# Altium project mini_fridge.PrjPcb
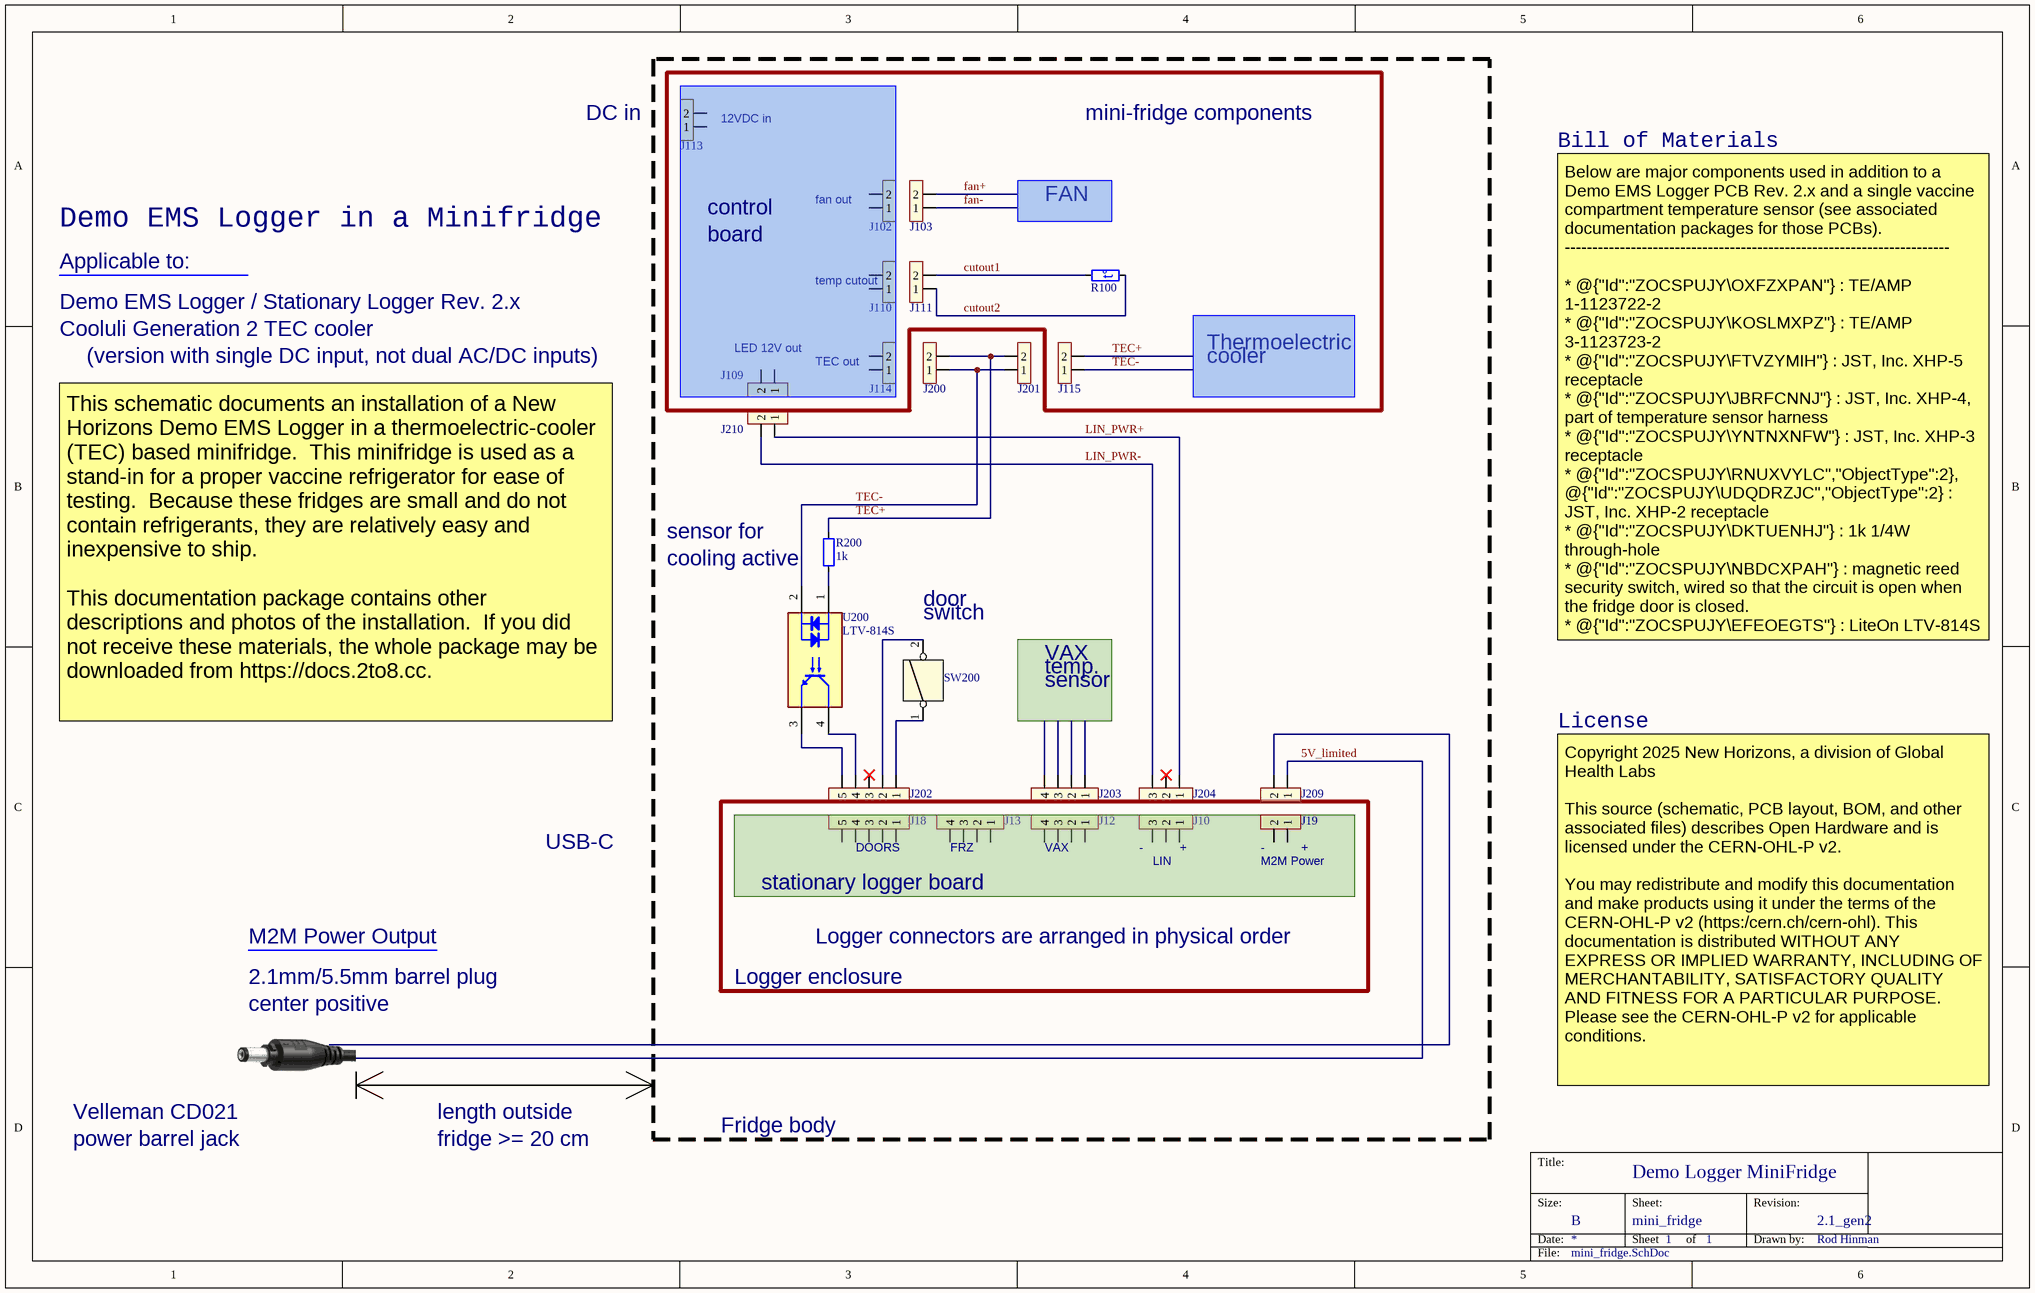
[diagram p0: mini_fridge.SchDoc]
nhToday: 2025-06-04; nhProjRev: 2.1_gen2; nhProjName: Demo Logger MiniFridge; nhEngPhone: +1 808-989-0977; nhEngName: Rod Hinman; nhEngEmail: rhinman@nhgh.org
1 sheet, 24 parts. Net scope: global (net labels, ports and power ports of the same name join across sheets).
Board file: mini_fridge.PcbDoc

## Sheet mini_fridge.SchDoc: Insert Title
size B; DrawnBy: Insert Name; Organization: NH-GG; DocumentNumber: 12345; Revision: 1; SheetNumber: 1; SheetTotal: 1; nhSheetName: mini_fridge

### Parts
J10  JST XH  [JST_S3B-XH-A(LF)(SN)]  (value not drawn)
J12  JST XH  [JST_B4B-XH-AM(LF)(SN)]  (value not drawn)
J13  JST XH  [JST_B4B-XH-AM(LF)(SN)]  (value not drawn)
J18  JST XH  [JST_S5B-XH-A(LF)(SN)]  (value not drawn)
J19  1x2 3.96mm  [AMP_1-1123723-2]  (value not drawn)
J102  1x2 3.96mm  [AMP_1-1123723-2]  (value not drawn)
J103  1x2 3.96mm  [AMP_1-1123723-2]  (value not drawn)
J109  1x2 3.96mm  [AMP_1-1123723-2]  (value not drawn)
J110  1x2 3.96mm  [AMP_1-1123723-2]  (value not drawn)
J111  1x2 3.96mm  [AMP_1-1123723-2]  (value not drawn)
J113  1x2 3.96mm  [AMP_1-1123723-2]  (value not drawn)
J114  1x2 3.96mm  [AMP_1-1123723-2]  (value not drawn)
J115  1x2 3.96mm  [AMP_1-1123723-2]  (value not drawn)
J200  1x2 3.96mm  [AMP_1-1123723-2]  (value not drawn)
J201  1x2 3.96mm  [AMP_1-1123723-2]  (value not drawn)
J202  JST XH  [JST_S5B-XH-A(LF)(SN)]  (value not drawn)
J203  JST XH  [JST_B4B-XH-AM(LF)(SN)]  (value not drawn)
J204  JST XH  [JST_S3B-XH-A(LF)(SN)]  (value not drawn)
J209  1x2 3.96mm  [AMP_1-1123723-2]  (value not drawn)
J210  1x2 3.96mm  [AMP_1-1123723-2]  (value not drawn)
R100  B2585:3435K 0402 1%  [RESC1005X40[0402]]  (value not drawn)
R200  value_text: 1k  [RESC1608X05AN[0603]]  (hidden comment: 1/10W 0603 1%)
SW200  SPST-NO Off-Mom  [CH_MX1A-11NW]  (value not drawn)
U200  LTV-814S  [DIP4_SMD]

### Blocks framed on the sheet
stationary logger board: J10 J12 J13 J18 J19

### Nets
5V_limited: J209.1
cutout1: J111.2 R100.1
cutout2: J111.1 R100.2
fan+: J103.2
fan-: J103.1
LIN_PWR+: J204.1 J210.1
LIN_PWR-: J204.3 J210.2
TEC+: J115.2 J200.2 J201.2 R200.1
TEC-: J115.1 J200.1 J201.1 U200.2(Cathode)
NetJ202_1: J202.1 SW200.1
NetJ202_2: J202.2 SW200.2
NetJ202_4: J202.4 U200.4(Collector)
NetJ202_5: J202.5 U200.3(Emitter)
NetR200_2: R200.2 U200.1(Anode)

Not connected (* = marked no-connect by the designer): J10 1 2 3; J12 1 2 3 4; J13 1 2 3 4; J18 1 2 3 4 5; J19 1 2; J102 1 2; J109 1 2; J110 1 2; J113 1 2; J114 1 2; J202 3*; J203 1 2 3 4; J204 2*; J209 2

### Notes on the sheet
- (near J113) DC in
- (near J113) 12VDC in
- mini-fridge components
- Bill of Materials
- Demo EMS Logger in a Minifridge
- control
- (near J102) fan out
- FAN
- Applicable to:
- board
- (near J110) temp cutout
- Demo EMS Logger / Stationary Logger Rev. 2.x
- Cooluli Generation 2 TEC cooler
- (version with single DC input, not dual AC/DC inputs)
- (near J109) LED 12V out
- (near J114) TEC out
- Thermoelectric
- cooler
- sensor for
- (near R200) cooling active
- (near SW200) door
- (near SW200) switch
- Below are major components used in addition to a Demo EMS Logger PCB Rev. 2.x and a single vaccine compartment temperature sensor (see associated documentation packages for those PCBs).
  ----------------------------------------------------------------------
  * @{"Id":"ZOCSPUJY\OXFZXPAN"} : TE/AMP 1-1123722-2
  * @{"Id":"ZOCSPUJY\KOSLMXPZ"} : TE/AMP 3-1123723-2
  * @{"Id":"ZOCSPUJY\FTVZYMIH"} : JST, Inc. XHP-5 receptacle
  * @{"Id":"ZOCSPUJY\JBRFCNNJ"} : JST, Inc. XHP-4, part of temperature sensor harness
  * @{"Id":"ZOCSPUJY\YNTNXNFW"} : JST, Inc. XHP-3 receptacle
  * @{"Id":"ZOCSPUJY\RNUXVYLC","ObjectType":2}, @{"Id":"ZOCSPUJY\UDQDRZJC","ObjectType":2} : JST, Inc. XHP-2 receptacle
  * @{"Id":"ZOCSPUJY\DKTUENHJ"} : 1k 1/4W through-hole
  * @{"Id":"ZOCSPUJY\NBDCXPAH"} : magnetic reed security switch, wired so that the circuit is open when the fridge door is closed.
  * @{"Id":"ZOCSPUJY\EFEOEGTS"} : LiteOn LTV-814S
  * power barrel cable: Tensility 10-01936
  Also suppplied to test laboratories for convenience, a power barrel jack with screw terminals: Velleman CD021.
- VAX
- temp.
- sensor
- This schematic documents an installation of a New Horizons Demo EMS Logger in a thermoelectric-cooler (TEC) based minifridge.  This minifridge is used as a stand-in for a proper vaccine refrigerator for ease of testing.  Because these fridges are small and do not contain refrigerants, they are relatively easy and inexpensive to ship.
  This documentation package contains other descriptions and photos of the installation.  If you did not receive these materials, the whole package may be downloaded from https://docs.2to8.cc.
- License
- USB-C
- (near J18) DOORS
- (near J13) FRZ
- (near J12) VAX
- (near J10) -
- (near J10) LIN
- (near J10) +
- (near J19) M2M Power
- (near J19) -
- (near J19) +
- M2M Power Output
- Logger connectors are arranged in physical order
- 2.1mm/5.5mm barrel plug
- center positive
- Logger enclosure
- Copyright 2025 New Horizons, a division of Global Health Labs
  This source (schematic, PCB layout, BOM, and other associated files) describes Open Hardware and is licensed under the CERN-OHL-P v2.
  You may redistribute and modify this documentation and make products using it under the terms of the CERN-OHL-P v2 (https:/cern.ch/cern-ohl). This documentation is distributed WITHOUT ANY EXPRESS OR IMPLIED WARRANTY, INCLUDING OF MERCHANTABILITY, SATISFACTORY QUALITY AND FITNESS FOR A PARTICULAR PURPOSE. Please see the CERN-OHL-P v2 for applicable conditions.
- power barrel jack
- Velleman CD021
- length outside
- fridge >= 20 cm
- Fridge body

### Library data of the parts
J10 J204 = CONN-00186: CONN HEADER R/A 3POS 2.5MM; manufacturer: JST Sales America Inc.; manufacturer_pn: S3B-XH-A(LF)(SN); id: 477185; reorder_quantity: 0
J12 J13 J203 = CONN-00064: 4 Positions Header, Shrouded Connector 0.098" (2.50mm) Through Hole Tin; manufacturer_pn: B4B-XH-AM(LF)(SN); manufacturer: JST Sales America Inc.; id: 139972; reorder_quantity: 0
J18 J202 = CONN-00187: CONN HEADER R/A 5POS 2.5MM; manufacturer_pn: S5B-XH-A(LF)(SN); manufacturer: JST Sales America Inc.; id: 477186; reorder_quantity: 0
J19 J102 J103 J109-J111 J113-J115 J200 J201 J209 J210 = CONN-00067: 2 Positions Header, Unshrouded Connector 0.156" (3.96mm) Through Hole Tin (blue); manufacturer_pn: 3-1123723-2; manufacturer: TE Connectivity AMP Connectors; id: 140460; reorder_quantity: 0
R100 = RES-00133: NTC Thermistor 10k 0402 (1005 Metric); manufacturer_pn: NTCG103JF103FT1; manufacturer: TDK Corporation; id: 225772; reorder_quantity: 0; value: 10000
R200 = RES-00016: RES SMD 1.00K OHM 1% 1/10W 0603; manufacturer_pn: CRCW06031K00FKEA; manufacturer: Vishay Dale; id: 137094; reorder_quantity: 0; value: 1000
SW200 = SW-00006: Pushbutton Switch SPST-NO Keyswitch Through Hole; manufacturer_pn: MX1A-11NW; manufacturer: Cherry Americas LLC; id: 141726; reorder_quantity: 0
U200 = ICXCV-00005: Optoisolator Transistor Output 5000Vrms 1 Channel 4-SMD; manufacturer: Lite-On Inc.; id: 141327; reorder_quantity: 0

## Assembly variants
as built: all parts fitted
